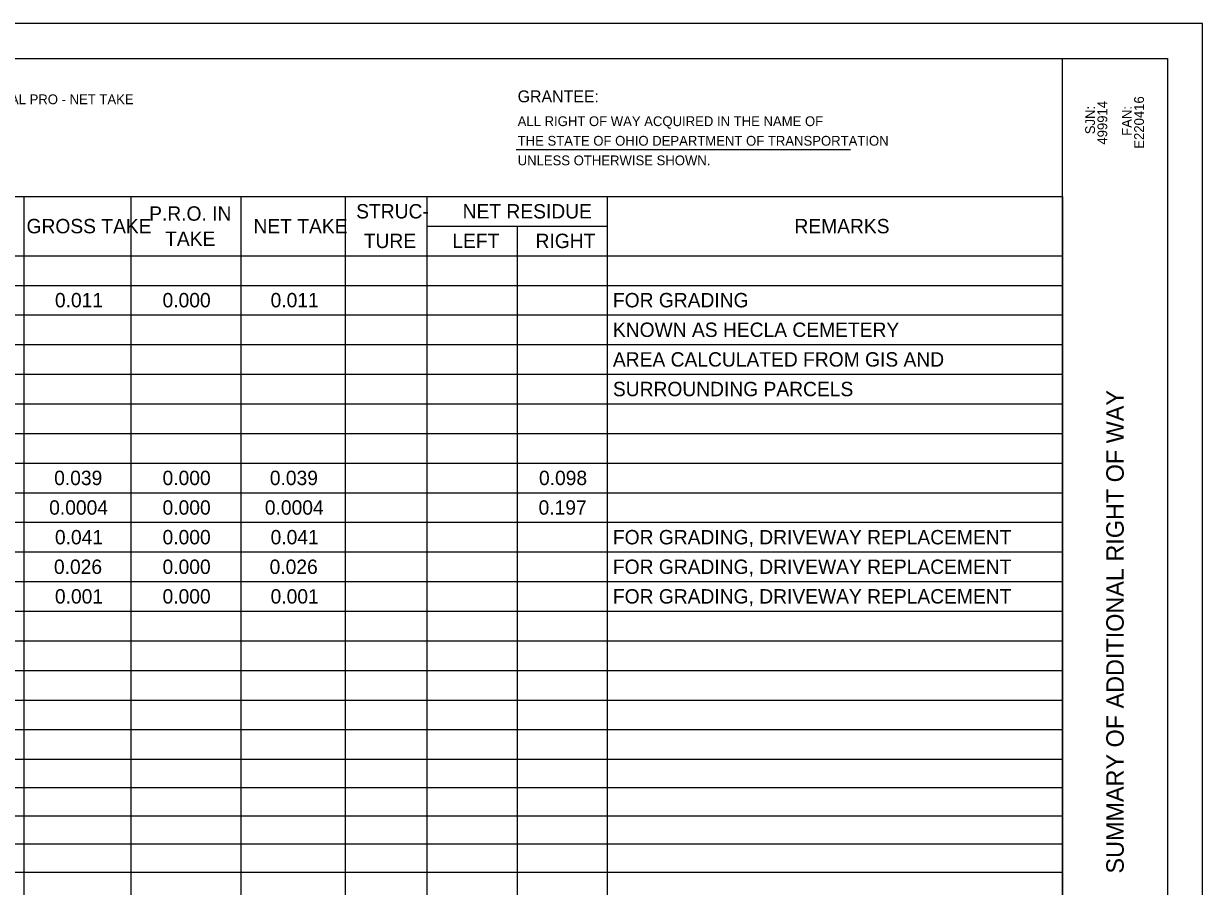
# Model space of a CAD drawing. Extents: x 0 to 34, y -1.2 to 22.
# Drawn here: x 17.14 to 34, y 9.67 to 22 of the extents above; entities that cross this region are included whole.
import ezdxf

# ---------------------------------------------------------------- set-up
doc = ezdxf.new("R2010")
doc.units = 0
for name, color, linetype in [('SH_Border', 7, 'Continuous'), ('SH_Cut_Line', 7, 'Continuous'), ('SH_Data', 7, 'Continuous'), ('SH_Text', 7, 'Continuous')]:
    doc.layers.add(name, color=color, linetype=linetype)

msp = doc.modelspace()

# ---------------------------------------------------------------- linework, layer by layer
at = {"layer": 'SH_Border'}
msp.add_line((32, 0.5), (32, 21.5), dxfattribs=at)
msp.add_lwpolyline([(1.5, 21.5), (33.5, 21.5), (33.5, 0.5), (1.5, 0.5)], close=True, dxfattribs=at)
at = {"layer": 'SH_Cut_Line'}
msp.add_lwpolyline([(0, 0), (34, 0), (34, 22), (0, 22)], close=True, dxfattribs=at)
at = {"layer": 'SH_Text'}
for p, q in [((24.186, 20.199), (28.967, 20.199)), ((1.501, 19.529), (32, 19.529)), ((17.144, 19.529), (17.144, 3.02)), ((18.676, 19.529), (18.676, 3.02)), ((20.248, 19.529), (20.248, 3.02)), ((21.74, 19.529), (21.74, 3.02)), ((22.909, 19.529), (22.909, 3.02)), ((25.489, 19.529), (25.489, 3.02)), ((32, 19.529), (32, 3.02)), ((22.909, 19.106), (25.489, 19.106)), ((24.199, 19.106), (24.199, 3.02)), ((1.501, 18.683), (32, 18.683)), ((1.501, 18.259), (32, 18.259)), ((1.501, 17.836), (32, 17.836)), ((1.501, 17.413), (32, 17.413)), ((1.501, 16.989), (32, 16.989)), ((1.501, 16.566), (32, 16.566)), ((1.501, 16.143), (32, 16.143)), ((1.501, 15.72), (32, 15.72)), ((1.501, 15.296), (32, 15.296)), ((1.501, 14.873), (32, 14.873)), ((1.501, 14.45), (32, 14.45)), ((1.501, 14.026), (32, 14.026)), ((1.501, 13.603), (32, 13.603)), ((1.501, 13.18), (32, 13.18)), ((1.501, 12.756), (32, 12.756)), ((1.501, 12.333), (32, 12.333)), ((1.501, 11.91), (32, 11.91)), ((1.501, 11.486), (32, 11.486)), ((1.501, 11.083), (32, 11.083)), ((1.501, 10.68), (32, 10.68)), ((1.501, 10.277), (32, 10.277)), ((1.501, 9.874), (32, 9.874))]:
    msp.add_line(p, q, dxfattribs=at)

# ---------------------------------------------------------------- texts
at = {"layer": 'SH_Data'}
msp.add_text('SUMMARY OF ADDITIONAL RIGHT OF WAY', height=0.25, rotation=90, dxfattribs=at).set_placement((32.875, 9.854))
at = {"layer": 'SH_Text'}
for s, height, p in [('NET RESIDUE = RECORD AREA - TOTAL PRO - NET TAKE', 0.14, (13.562, 20.848)), ('GRANTEE:', 0.17, (24.208, 20.875)), ('ALL RIGHT OF WAY ACQUIRED IN THE NAME OF', 0.14, (24.208, 20.535)), ('THE STATE OF OHIO DEPARTMENT OF TRANSPORTATION', 0.14, (24.208, 20.255)), ('UNLESS OTHERWISE SHOWN.', 0.14, (24.208, 19.975)), ('P.R.O. IN ', 0.2056, (18.938, 19.183)), ('STRUC-', 0.2056, (21.899, 19.215)), ('NET RESIDUE', 0.20561, (23.421, 19.215)), ('GROSS TAKE', 0.2056, (17.185, 19.003)), ('NET TAKE', 0.2056, (20.43, 19.003)), ('REMARKS', 0.2056, (28.166, 19.003)), ('TAKE', 0.2056, (19.167, 18.823)), ('TURE', 0.2056, (22.007, 18.792)), ('LEFT', 0.2056, (23.273, 18.792)), ('RIGHT', 0.2056, (24.464, 18.792)), ('0.011', 0.2056, (17.591, 17.945)), ('0.000', 0.2056, (19.13, 17.945)), ('0.011', 0.2056, (20.675, 17.945)), ('FOR GRADING', 0.20561, (25.57, 17.945)), ('KNOWN AS HECLA CEMETERY', 0.20561, (25.57, 17.522)), ('AREA CALCULATED FROM GIS AND', 0.20561, (25.57, 17.098)), ('SURROUNDING PARCELS', 0.20561, (25.57, 16.675)), ('0.039', 0.2056, (17.58, 15.405)), ('0.000', 0.2056, (19.13, 15.405)), ('0.039', 0.2056, (20.664, 15.405)), ('0.098', 0.2056, (24.513, 15.405)), ('0.0004', 0.2056, (17.509, 14.982)), ('0.000', 0.2056, (19.13, 14.982)), ('0.0004', 0.2056, (20.593, 14.982)), ('0.197', 0.2056, (24.507, 14.982)), ('0.041', 0.2056, (17.591, 14.558)), ('0.000', 0.2056, (19.13, 14.558)), ('0.041', 0.2056, (20.675, 14.558)), ('FOR GRADING, DRIVEWAY REPLACEMENT', 0.20561, (25.57, 14.558)), ('0.026', 0.2056, (17.577, 14.135)), ('0.000', 0.2056, (19.13, 14.135)), ('0.026', 0.2056, (20.661, 14.135)), ('FOR GRADING, DRIVEWAY REPLACEMENT', 0.20561, (25.57, 14.135)), ('0.001', 0.2056, (17.591, 13.712)), ('0.000', 0.2056, (19.13, 13.712)), ('0.001', 0.2056, (20.675, 13.712)), ('FOR GRADING, DRIVEWAY REPLACEMENT', 0.20561, (25.57, 13.712))]:
    msp.add_text(s, height=height, dxfattribs=at).set_placement(p)
for s, p in [('E220416', (33.164, 20.212)), ('SJN:', (32.464, 20.419)), ('499914', (32.639, 20.27)), ('FAN:', (32.989, 20.396))]:
    msp.add_text(s, height=0.14, rotation=90, dxfattribs=at).set_placement(p)

doc.saveas('drawing.dxf')
